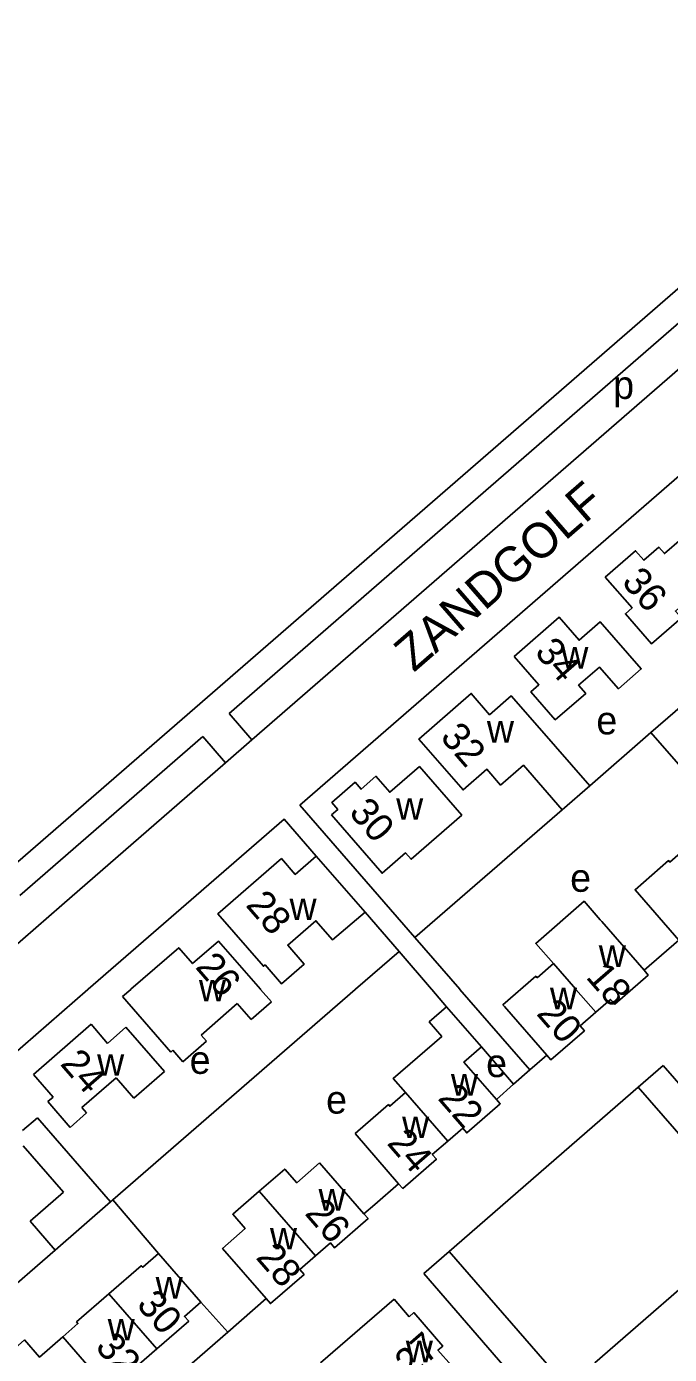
# Model space of a CAD drawing. Extents: x 155854 to 157362, y 383621 to 384685.
# Drawn here: x 156448.5 to 156540.2, y 384447.9 to 384637.3 of the extents above; entities that cross this region are included whole.
import ezdxf

# ---------------------------------------------------------------- set-up
doc = ezdxf.new("R2010")
doc.units = 0
for name, color, linetype in [('BLT_Basislijn', 7, 'Continuous'), ('BLT_Bebouwing', 7, 'Continuous'), ('BLT_Centroide', 7, 'Continuous'), ('BLT_Huisnummer', 7, 'Continuous'), ('BLT_Huisnummer_ tussenligend', 7, 'Continuous'), ('BLT_Onderverdeling_panden', 7, 'Continuous'), ('BLT_Straatnaam', 7, 'Continuous')]:
    doc.layers.add(name, color=color, linetype=linetype)

msp = doc.modelspace()

# ---------------------------------------------------------------- linework, layer by layer
at = {"layer": 'BLT_Basislijn'}
for p, q in [((156487.51, 384526.25), (156562.25, 384591.18)), ((156537.55, 384536.61), (156578.65, 384572.31)), ((156480.66, 384535.59), (156477.41, 384539.32)), ((156476.89, 384532.31), (156473.64, 384536.04)), ((156528.88, 384529.03), (156537.55, 384536.61)), ((156537.55, 384536.61), (156544.16, 384529.09)), ((156503.9, 384507.38), (156487.51, 384526.25)), ((156503.9, 384507.38), (156524.91, 384525.6)), ((156439.76, 384500), (156453.52, 384512.02)), ((156510.31, 384500), (156503.9, 384507.38)), ((156495.41, 384500), (156501.64, 384505.41)), ((156501.64, 384505.41), (156506.28, 384500)), ((156541.56, 384507.03), (156536.6, 384502.72)), ((156437.14, 384482.49), (156457.27, 384499.98)), ((156460.83, 384469.96), (156495.39, 384499.98)), ((156495.39, 384499.98), (156495.41, 384500)), ((156506.28, 384500), (156506.3, 384499.98)), ((156506.3, 384499.98), (156508.43, 384497.5)), ((156510.33, 384499.98), (156510.31, 384500)), ((156517.99, 384486.47), (156520.3, 384488.5)), ((156535.74, 384486.05), (156539.31, 384489.12)), ((156539.31, 384489.12), (156572.16, 384451.43)), ((156508.8, 384462.59), (156535.74, 384486.05)), ((156568.62, 384448.35), (156535.74, 384486.05)), ((156501.58, 384472.27), (156498.2, 384469.31)), ((156460.83, 384469.96), (156460.49, 384469.71)), ((156460.83, 384469.96), (156467.34, 384462.32)), ((156498.2, 384469.31), (156496.63, 384467.96)), ((156406.16, 384422.46), (156452.57, 384462.81)), ((156505.19, 384459.46), (156508.8, 384462.59)), ((156541.64, 384424.92), (156508.8, 384462.59)), ((156505.19, 384459.46), (156537.93, 384421.71)), ((156473.37, 384455.39), (156477.23, 384451.09)), ((156482.69, 384455.88), (156477.23, 384451.09))]:
    msp.add_line(p, q, dxfattribs=at)
for points in [[(156426.29, 384500), (156571.71, 384626.22), (156580.21, 384637.32)], [(156477.41, 384539.32), (156577.82, 384626.56)], [(156480.66, 384535.59), (156581.09, 384622.79)], [(156447.54, 384513.37), (156473.64, 384536.04)], [(156476.89, 384532.31), (156480.66, 384535.59)], [(156453.52, 384512.02), (156476.89, 384532.31)], [(156457.29, 384500), (156485.24, 384524.28), (156489.83, 384518.99)], [(156496.79, 384510.99), (156501.64, 384505.41)], [(156457.27, 384499.98), (156457.29, 384500)], [(156522.71, 384490.63), (156520.3, 384488.5), (156510.33, 384499.98)], [(156515.53, 384484.3), (156517.99, 384486.47), (156513.39, 384491.78)], [(156477.23, 384451.09), (156422.55, 384403.59)]]:
    msp.add_lwpolyline(points, dxfattribs=at)
msp.add_lwpolyline([(156539.82, 384434.95), (156559.04, 384451.74), (156548.85, 384463.47), (156529.59, 384446.72)], close=True, dxfattribs=at)
at = {"layer": 'BLT_Bebouwing'}
for p, q in [((156528.88, 384529.03), (156524.91, 384525.6)), ((156462.21, 384498.98), (156463.37, 384499.98)), ((156481.87, 384499.98), (156483.43, 384498.2)), ((156469.1, 384491.05), (156462.21, 384498.98)), ((156478.57, 384497.96), (156473.41, 384493.46)), ((156480.54, 384495.69), (156478.57, 384497.96)), ((156483.43, 384498.2), (156480.54, 384495.69)), ((156449.49, 384487.86), (156457.7, 384495.01)), ((156457.7, 384495.01), (156460.07, 384492.28)), ((156460.07, 384492.28), (156462.69, 384494.6)), ((156462.69, 384494.6), (156468.19, 384488.28)), ((156474.16, 384492.59), (156470.8, 384489.67)), ((156473.41, 384493.46), (156474.16, 384492.59)), ((156469.39, 384491.3), (156469.1, 384491.05)), ((156470.8, 384489.67), (156469.39, 384491.3)), ((156452.29, 384484.64), (156449.49, 384487.86)), ((156461.28, 384487.37), (156456.41, 384483.14)), ((156463.8, 384484.47), (156461.28, 384487.37)), ((156468.19, 384488.28), (156463.8, 384484.47)), ((156451.52, 384483.98), (156452.29, 384484.64)), ((156454.71, 384480.31), (156451.52, 384483.98)), ((156456.41, 384483.14), (156457.08, 384482.37)), ((156450.09, 384481.68), (156447.94, 384479.84)), ((156460.49, 384469.71), (156450.09, 384481.68)), ((156457.08, 384482.37), (156454.71, 384480.31)), ((156501.58, 384472.27), (156495.37, 384479.44)), ((156448.01, 384477.66), (156453.76, 384471.05)), ((156496.63, 384467.96), (156490.29, 384475.25)), ((156453.76, 384471.05), (156449, 384466.91)), ((156449, 384466.91), (156452.57, 384462.81)), ((156473.37, 384455.39), (156467.34, 384462.32)), ((156490.46, 384446.71), (156500.97, 384455.82)), ((156500.97, 384455.82), (156503.07, 384453.3))]:
    msp.add_line(p, q, dxfattribs=at)
for points in [[(156531.07, 384558.8), (156534.9, 384554.4), (156533.94, 384553.57), (156537.66, 384549.29), (156541.92, 384552.99), (156541.07, 384553.96), (156543.33, 384555.92), (156545.37, 384553.57), (156548.69, 384556.46), (156541.92, 384564.25), (156539.51, 384562.15), (156538.72, 384563.06), (156536.57, 384561.19), (156535.39, 384562.55)], [(156518.06, 384547.49), (156524.49, 384553.07), (156527.33, 384549.79), (156530.35, 384552.41), (156536.19, 384545.69), (156532.93, 384542.86), (156530.24, 384545.95), (156527.27, 384543.37), (156528.28, 384542.21), (156523.94, 384538.44), (156520.46, 384542.45), (156521.59, 384543.43)], [(156492.01, 384524.88), (156492.91, 384525.66), (156492.06, 384526.65), (156495.37, 384529.53), (156496.23, 384528.54), (156498.35, 384530.38), (156500.32, 384528.11), (156504.55, 384531.78), (156510.59, 384524.84), (156503.36, 384518.56), (156502.57, 384519.46), (156499.23, 384516.56)]]:
    msp.add_lwpolyline(points, close=True, dxfattribs=at)
for points in [[(156524.91, 384525.6), (156519.38, 384531.95), (156516.13, 384529.13), (156514.17, 384531.39), (156510.77, 384528.44), (156504.47, 384535.69), (156511.95, 384542.2), (156514.57, 384539.16), (156517.66, 384541.85), (156521.34, 384537.62), (156528.88, 384529.03)], [(156489.83, 384518.99), (156486.83, 384516.39), (156484.86, 384518.65), (156475.8, 384510.78), (156482.3, 384503.28), (156482.53, 384503.49), (156484.89, 384500.78), (156488.12, 384503.59), (156485.77, 384506.3), (156489.78, 384509.78), (156492.13, 384507.07), (156496.79, 384510.99)], [(156496.79, 384510.99), (156489.83, 384518.99)], [(156542.63, 384520.16), (156540.3, 384518.13), (156540.11, 384518.36), (156535.32, 384514.19), (156541.56, 384507.03)], [(156523.68, 384503.67), (156521.14, 384506.54), (156528.04, 384512.55), (156530.36, 384509.89), (156530.56, 384509.66), (156536.6, 384502.72)], [(156463.39, 384500), (156470.22, 384505.93), (156472.18, 384503.66), (156475.88, 384506.88), (156481.86, 384500)], [(156521.34, 384501.63), (156523.68, 384503.67)], [(156522.71, 384490.63), (156516.67, 384497.57), (156516.47, 384497.79), (156521.14, 384501.86), (156521.34, 384501.63)], [(156536.6, 384502.72), (156537.19, 384502.03), (156532.42, 384497.86), (156531.81, 384498.56), (156529.71, 384496.72)], [(156463.37, 384499.98), (156463.39, 384500)], [(156481.86, 384500), (156481.87, 384499.98)], [(156502.57, 384485.28), (156500.8, 384487.26), (156507.73, 384493.28), (156505.95, 384495.34), (156508.43, 384497.5)], [(156508.43, 384497.5), (156513.39, 384491.78)], [(156529.71, 384496.72), (156527.47, 384494.78), (156528.08, 384494.09), (156523.3, 384489.93), (156522.71, 384490.63)], [(156513.39, 384491.78), (156510.91, 384489.62), (156515.53, 384484.3)], [(156495.37, 384479.44), (156500.12, 384483.55), (156500.32, 384483.33), (156502.57, 384485.28)], [(156515.53, 384484.3), (156516.08, 384483.67), (156511.3, 384479.51), (156510.73, 384480.2), (156508.59, 384478.35)], [(156508.59, 384478.35), (156506.39, 384476.43), (156506.98, 384475.75), (156502.18, 384471.6), (156501.58, 384472.27)], [(156490.29, 384475.25), (156487.06, 384472.4), (156485.35, 384474.36), (156481.71, 384471.2)], [(156452.57, 384462.81), (156460.49, 384469.71)], [(156481.71, 384471.2), (156477.93, 384467.92), (156479.69, 384465.9), (156476.46, 384463.05), (156482.69, 384455.88)], [(156489.72, 384461.97), (156491.85, 384463.82), (156492.45, 384463.12), (156497.23, 384467.29), (156496.63, 384467.96)], [(156467.34, 384462.32), (156465.07, 384460.35), (156464.87, 384460.57), (156460.26, 384456.57)], [(156482.69, 384455.88), (156483.3, 384455.18), (156488.1, 384459.33), (156487.49, 384460.04), (156489.72, 384461.97)], [(156460.26, 384456.57), (156455.64, 384452.55), (156455.83, 384452.32), (156453.67, 384450.44)], [(156467.09, 384448.72), (156471.64, 384452.68), (156471.03, 384453.35), (156473.37, 384455.39)], [(156509.11, 384446.34), (156507.2, 384448.53), (156507.88, 384449.12), (156503.74, 384453.9), (156503.07, 384453.3)], [(156453.67, 384450.44), (156450.34, 384447.55), (156448.21, 384449.99), (156444.63, 384446.89), (156446.68, 384444.76)], [(156459.7, 384443.5), (156461.81, 384445.34), (156462.4, 384444.64), (156467.09, 384448.72)]]:
    msp.add_lwpolyline(points, dxfattribs=at)
at = {"layer": 'BLT_Onderverdeling_panden'}
for p, q in [((156526.86, 384500), (156523.68, 384503.67)), ((156526.88, 384499.98), (156526.86, 384500)), ((156529.71, 384496.72), (156526.88, 384499.98)), ((156508.59, 384478.35), (156502.57, 384485.28)), ((156489.72, 384461.97), (156481.71, 384471.2)), ((156467.09, 384448.72), (156460.26, 384456.57)), ((156459.7, 384443.5), (156453.67, 384450.44))]:
    msp.add_line(p, q, dxfattribs=at)

# ---------------------------------------------------------------- texts
at = {"layer": 'BLT_Centroide'}
for s, p in [('p', (156532.2, 384584.21)), ('w', (156524.79, 384545.75)), ('e', (156529.8, 384536.36)), ('w', (156514.18, 384535.19)), ('w', (156501.23, 384524.19)), ('e', (156526.06, 384513.91)), ('w', (156486.02, 384509.88)), ('w', (156530.14, 384503.19)), ('w', (156473.09, 384498.28)), ('w', (156523.18, 384497.16)), ('w', (156458.57, 384487.66)), ('e', (156471.78, 384487.94)), ('e', (156514.07, 384487.48)), ('w', (156509.05, 384484.83)), ('e', (156491.24, 384482.27)), ('w', (156502.08, 384478.78)), ('w', (156490.16, 384468.44)), ('w', (156483.23, 384462.89)), ('w', (156466.92, 384455.88)), ('w', (156460.08, 384449.92)), ('w', (156502.61, 384446.8))]:
    msp.add_text(s, height=4, dxfattribs=at).set_placement(p)
at = {"layer": 'BLT_Huisnummer'}
for s, rotation, p in [('34', 310.9758, (156520.86, 384548)), ('30', 310.9708, (156494.37, 384525.14)), ('28', 310.9823, (156479.65, 384511.95)), ('26', 310.9801, (156472.46, 384503.12)), ('18', 310.985, (156528.18, 384501.7)), ('20', 310.985, (156521.13, 384496.47)), ('24', 310.979, (156453.18, 384489.31)), ('22', 310.9815, (156507.05, 384484.39)), ('24', 310.9815, (156499.8, 384477.99)), ('26', 310.9815, (156488.07, 384467.98)), ('28', 310.9815, (156481.09, 384461.69)), ('30', 310.985, (156464.06, 384454.95)), ('27', 40.9815, (156503.23, 384444.49))]:
    msp.add_text(s, height=4, rotation=rotation, dxfattribs=at).set_placement(p)
at = {"layer": 'BLT_Huisnummer_ tussenligend'}
for s, rotation, p in [('36', 310.9803, (156533.28, 384558.02)), ('32', 310.9787, (156507.39, 384535.89)), ('32', 310.985, (156458.17, 384448.91))]:
    msp.add_text(s, height=4, rotation=rotation, dxfattribs=at).set_placement(p)
at = {"layer": 'BLT_Straatnaam'}
msp.add_text('ZANDGOLF', height=5, rotation=40.9818, dxfattribs=at).set_placement((156503.75, 384545.13))

doc.saveas('drawing.dxf')
